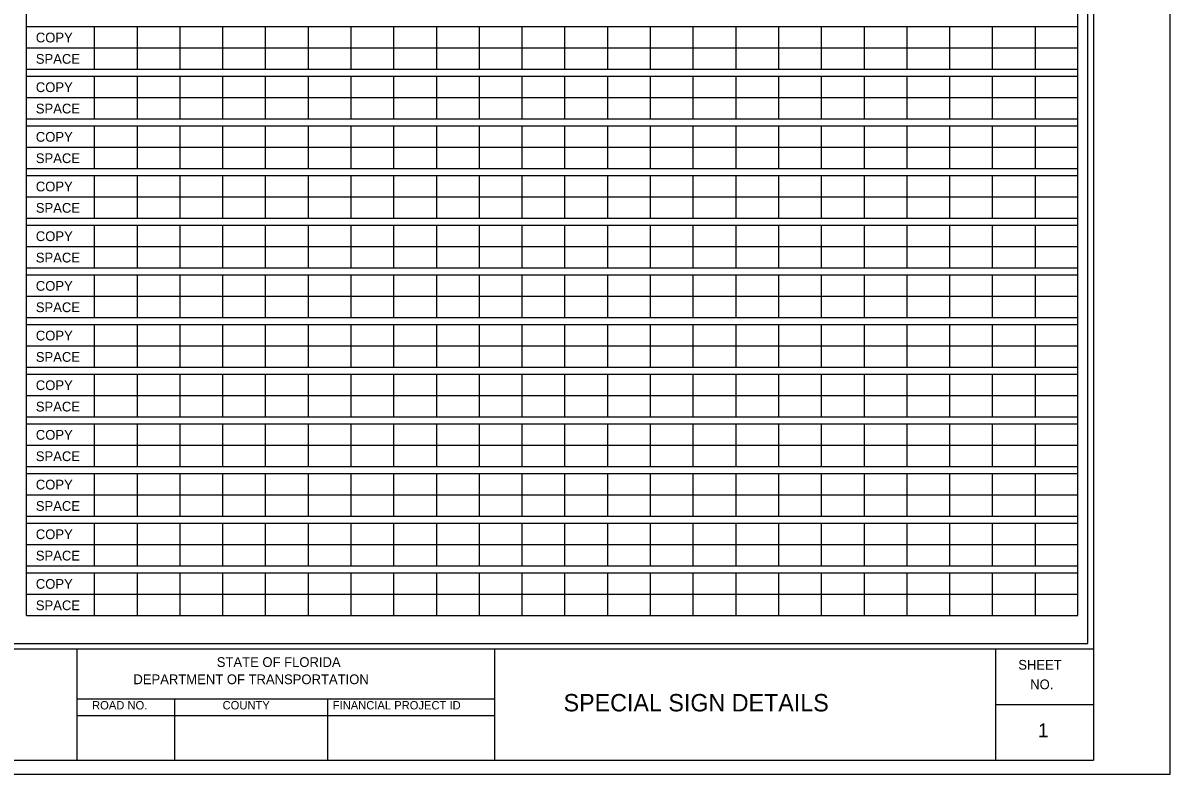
# Model space of a CAD drawing. Extents: x 17890484 to 17890754, y 17897495 to 17897992.
# Drawn here: x 17890564.9 to 17890645.6, y 17897495 to 17897547.8 of the extents above; entities that cross this region are included whole.
import ezdxf

# ---------------------------------------------------------------- set-up
doc = ezdxf.new("R2010")
doc.units = 0
for name, color, linetype in [('PlotBorder_dp', 7, 'Continuous'), ('SheetBorder_dp', 7, 'Continuous'), ('SheetLines_dp', 7, 'Continuous'), ('SheetLinesMisc1_dp', 7, 'Continuous'), ('SheetLinesMisc2_dp', 7, 'Continuous'), ('TextMinor', 7, 'Continuous'), ('TextMisc', 7, 'Continuous'), ('TextShtNo', 7, 'Continuous')]:
    doc.layers.add(name, color=color, linetype=linetype)

msp = doc.modelspace()

# ---------------------------------------------------------------- linework, layer by layer
at = {"layer": 'PlotBorder_dp'}
msp.add_lwpolyline([(17890483.9, 17897494.956), (17890645.649, 17897494.956), (17890645.649, 17897598.868), (17890483.9, 17897598.868)], close=True, dxfattribs=at)
at = {"layer": 'SheetBorder_dp'}
for p, q in [((17890640.258, 17897597.887), (17890640.258, 17897495.936)), ((17890489.292, 17897503.779), (17890640.258, 17897503.779)), ((17890489.292, 17897495.936), (17890640.258, 17897495.936))]:
    msp.add_line(p, q, dxfattribs=at)
at = {"layer": 'SheetLines_dp'}
for p, q in [((17890568.696, 17897503.779), (17890568.696, 17897495.936)), ((17890598.105, 17897495.936), (17890598.105, 17897503.779)), ((17890633.395, 17897495.936), (17890633.395, 17897503.779)), ((17890568.696, 17897500.25), (17890598.105, 17897500.25)), ((17890575.558, 17897500.25), (17890575.558, 17897495.936)), ((17890586.341, 17897500.25), (17890586.341, 17897495.936)), ((17890633.395, 17897499.858), (17890640.258, 17897499.858)), ((17890568.696, 17897499.073), (17890598.105, 17897499.073))]:
    msp.add_line(p, q, dxfattribs=at)
at = {"layer": 'SheetLinesMisc1_dp'}
for p, q in [((17890565.155, 17897547.581), (17890639.157, 17897547.581)), ((17890569.918, 17897547.581), (17890569.918, 17897544.575)), ((17890572.929, 17897547.581), (17890572.929, 17897544.575)), ((17890575.94, 17897547.581), (17890575.94, 17897544.575)), ((17890578.949, 17897547.581), (17890578.949, 17897544.575)), ((17890581.96, 17897547.581), (17890581.96, 17897544.575)), ((17890584.97, 17897547.581), (17890584.97, 17897544.575)), ((17890587.981, 17897547.581), (17890587.981, 17897544.575)), ((17890590.991, 17897547.581), (17890590.991, 17897544.575)), ((17890594.001, 17897547.581), (17890594.001, 17897544.575)), ((17890597.011, 17897547.581), (17890597.011, 17897544.575)), ((17890600.022, 17897547.581), (17890600.022, 17897544.575)), ((17890603.032, 17897547.581), (17890603.032, 17897544.575)), ((17890606.043, 17897547.581), (17890606.043, 17897544.575)), ((17890609.053, 17897547.581), (17890609.053, 17897544.575)), ((17890612.064, 17897547.581), (17890612.064, 17897544.575)), ((17890615.074, 17897547.581), (17890615.074, 17897544.575)), ((17890618.084, 17897547.581), (17890618.084, 17897544.575)), ((17890621.094, 17897547.581), (17890621.094, 17897544.575)), ((17890624.105, 17897547.581), (17890624.105, 17897544.575)), ((17890627.116, 17897547.581), (17890627.116, 17897544.575)), ((17890630.125, 17897547.581), (17890630.125, 17897544.575)), ((17890633.136, 17897547.581), (17890633.136, 17897544.575)), ((17890636.147, 17897547.581), (17890636.147, 17897544.575)), ((17890565.155, 17897546.078), (17890639.157, 17897546.078)), ((17890565.155, 17897544.575), (17890639.157, 17897544.575)), ((17890565.155, 17897544.084), (17890639.157, 17897544.084)), ((17890569.918, 17897544.084), (17890569.918, 17897541.078)), ((17890572.929, 17897544.084), (17890572.929, 17897541.078)), ((17890575.94, 17897544.084), (17890575.94, 17897541.078)), ((17890578.949, 17897544.084), (17890578.949, 17897541.078)), ((17890581.96, 17897544.084), (17890581.96, 17897541.078)), ((17890584.97, 17897544.084), (17890584.97, 17897541.078)), ((17890587.981, 17897544.084), (17890587.981, 17897541.078)), ((17890590.991, 17897544.084), (17890590.991, 17897541.078)), ((17890594.001, 17897544.084), (17890594.001, 17897541.078)), ((17890597.011, 17897544.084), (17890597.011, 17897541.078)), ((17890600.022, 17897544.084), (17890600.022, 17897541.078)), ((17890603.032, 17897544.084), (17890603.032, 17897541.078)), ((17890606.043, 17897544.084), (17890606.043, 17897541.078)), ((17890609.053, 17897544.084), (17890609.053, 17897541.078)), ((17890612.064, 17897544.084), (17890612.064, 17897541.078)), ((17890615.074, 17897544.084), (17890615.074, 17897541.078)), ((17890618.084, 17897544.084), (17890618.084, 17897541.078)), ((17890621.094, 17897544.084), (17890621.094, 17897541.078)), ((17890624.105, 17897544.084), (17890624.105, 17897541.078)), ((17890627.116, 17897544.084), (17890627.116, 17897541.078)), ((17890630.125, 17897544.084), (17890630.125, 17897541.078)), ((17890633.136, 17897544.084), (17890633.136, 17897541.078)), ((17890636.147, 17897544.084), (17890636.147, 17897541.078)), ((17890565.155, 17897542.581), (17890639.157, 17897542.581)), ((17890565.155, 17897541.078), (17890639.157, 17897541.078)), ((17890565.155, 17897540.588), (17890639.157, 17897540.588)), ((17890569.918, 17897540.588), (17890569.918, 17897537.582)), ((17890572.929, 17897540.588), (17890572.929, 17897537.582)), ((17890575.94, 17897540.588), (17890575.94, 17897537.582)), ((17890578.949, 17897540.588), (17890578.949, 17897537.582)), ((17890581.96, 17897540.588), (17890581.96, 17897537.582)), ((17890584.97, 17897540.588), (17890584.97, 17897537.582)), ((17890587.981, 17897540.588), (17890587.981, 17897537.582)), ((17890590.991, 17897540.588), (17890590.991, 17897537.582)), ((17890594.001, 17897540.588), (17890594.001, 17897537.582)), ((17890597.011, 17897540.588), (17890597.011, 17897537.582)), ((17890600.022, 17897540.588), (17890600.022, 17897537.582)), ((17890603.032, 17897540.588), (17890603.032, 17897537.582)), ((17890606.043, 17897540.588), (17890606.043, 17897537.582)), ((17890609.053, 17897540.588), (17890609.053, 17897537.582)), ((17890612.064, 17897540.588), (17890612.064, 17897537.582)), ((17890615.074, 17897540.588), (17890615.074, 17897537.582)), ((17890618.084, 17897540.588), (17890618.084, 17897537.582)), ((17890621.094, 17897540.588), (17890621.094, 17897537.582)), ((17890624.105, 17897540.588), (17890624.105, 17897537.582)), ((17890627.116, 17897540.588), (17890627.116, 17897537.582)), ((17890630.125, 17897540.588), (17890630.125, 17897537.582)), ((17890633.136, 17897540.588), (17890633.136, 17897537.582)), ((17890636.147, 17897540.588), (17890636.147, 17897537.582)), ((17890565.155, 17897539.085), (17890639.157, 17897539.085)), ((17890565.155, 17897537.582), (17890639.157, 17897537.582)), ((17890565.155, 17897537.091), (17890639.157, 17897537.091)), ((17890569.918, 17897537.091), (17890569.918, 17897534.085)), ((17890572.929, 17897537.091), (17890572.929, 17897534.085)), ((17890575.94, 17897537.091), (17890575.94, 17897534.085)), ((17890578.949, 17897537.091), (17890578.949, 17897534.085)), ((17890581.96, 17897537.091), (17890581.96, 17897534.085)), ((17890584.97, 17897537.091), (17890584.97, 17897534.085)), ((17890587.981, 17897537.091), (17890587.981, 17897534.085)), ((17890590.991, 17897537.091), (17890590.991, 17897534.085)), ((17890594.001, 17897537.091), (17890594.001, 17897534.085)), ((17890597.011, 17897537.091), (17890597.011, 17897534.085)), ((17890600.022, 17897537.091), (17890600.022, 17897534.085)), ((17890603.032, 17897537.091), (17890603.032, 17897534.085)), ((17890606.043, 17897537.091), (17890606.043, 17897534.085)), ((17890609.053, 17897537.091), (17890609.053, 17897534.085)), ((17890612.064, 17897537.091), (17890612.064, 17897534.085)), ((17890615.074, 17897537.091), (17890615.074, 17897534.085)), ((17890618.084, 17897537.091), (17890618.084, 17897534.085)), ((17890621.094, 17897537.091), (17890621.094, 17897534.085)), ((17890624.105, 17897537.091), (17890624.105, 17897534.085)), ((17890627.116, 17897537.091), (17890627.116, 17897534.085)), ((17890630.125, 17897537.091), (17890630.125, 17897534.085)), ((17890633.136, 17897537.091), (17890633.136, 17897534.085)), ((17890636.147, 17897537.091), (17890636.147, 17897534.085)), ((17890565.155, 17897535.588), (17890639.157, 17897535.589)), ((17890565.155, 17897534.085), (17890639.157, 17897534.085)), ((17890565.155, 17897533.595), (17890639.157, 17897533.595)), ((17890569.918, 17897533.595), (17890569.918, 17897530.589)), ((17890572.929, 17897533.595), (17890572.929, 17897530.589)), ((17890575.94, 17897533.595), (17890575.94, 17897530.589)), ((17890578.949, 17897533.595), (17890578.949, 17897530.589)), ((17890581.96, 17897533.595), (17890581.96, 17897530.589)), ((17890584.97, 17897533.595), (17890584.97, 17897530.589)), ((17890587.981, 17897533.595), (17890587.981, 17897530.589)), ((17890590.991, 17897533.595), (17890590.991, 17897530.589)), ((17890594.001, 17897533.595), (17890594.001, 17897530.589)), ((17890597.011, 17897533.595), (17890597.011, 17897530.589)), ((17890600.022, 17897533.595), (17890600.022, 17897530.589)), ((17890603.032, 17897533.595), (17890603.032, 17897530.589)), ((17890606.043, 17897533.595), (17890606.043, 17897530.589)), ((17890609.053, 17897533.595), (17890609.053, 17897530.589)), ((17890612.064, 17897533.595), (17890612.064, 17897530.589)), ((17890615.074, 17897533.595), (17890615.074, 17897530.589)), ((17890618.084, 17897533.595), (17890618.084, 17897530.589)), ((17890621.094, 17897533.595), (17890621.094, 17897530.589)), ((17890624.105, 17897533.595), (17890624.105, 17897530.589)), ((17890627.116, 17897533.595), (17890627.116, 17897530.589)), ((17890630.125, 17897533.595), (17890630.125, 17897530.589)), ((17890633.136, 17897533.595), (17890633.136, 17897530.589)), ((17890636.147, 17897533.595), (17890636.147, 17897530.589)), ((17890565.155, 17897532.092), (17890639.157, 17897532.092)), ((17890565.155, 17897530.589), (17890639.157, 17897530.589)), ((17890565.155, 17897530.099), (17890639.157, 17897530.099)), ((17890569.918, 17897530.099), (17890569.918, 17897527.092)), ((17890572.929, 17897530.099), (17890572.929, 17897527.092)), ((17890575.94, 17897530.099), (17890575.94, 17897527.092)), ((17890578.949, 17897530.099), (17890578.949, 17897527.092)), ((17890581.96, 17897530.099), (17890581.96, 17897527.092)), ((17890584.97, 17897530.099), (17890584.97, 17897527.092)), ((17890587.981, 17897530.099), (17890587.981, 17897527.092)), ((17890590.991, 17897530.099), (17890590.991, 17897527.092)), ((17890594.001, 17897530.099), (17890594.001, 17897527.092)), ((17890597.011, 17897530.099), (17890597.011, 17897527.092)), ((17890600.022, 17897530.099), (17890600.022, 17897527.092)), ((17890603.032, 17897530.099), (17890603.032, 17897527.092)), ((17890606.043, 17897530.099), (17890606.043, 17897527.092)), ((17890609.053, 17897530.099), (17890609.053, 17897527.092)), ((17890612.064, 17897530.099), (17890612.064, 17897527.092)), ((17890615.074, 17897530.099), (17890615.074, 17897527.092)), ((17890618.084, 17897530.099), (17890618.084, 17897527.092)), ((17890621.094, 17897530.099), (17890621.094, 17897527.092)), ((17890624.105, 17897530.099), (17890624.105, 17897527.092)), ((17890627.116, 17897530.099), (17890627.116, 17897527.092)), ((17890630.125, 17897530.099), (17890630.125, 17897527.092)), ((17890633.136, 17897530.099), (17890633.136, 17897527.092)), ((17890636.147, 17897530.099), (17890636.147, 17897527.092)), ((17890565.155, 17897528.595), (17890639.157, 17897528.595)), ((17890565.155, 17897527.092), (17890639.157, 17897527.092)), ((17890565.155, 17897526.602), (17890639.157, 17897526.602)), ((17890569.918, 17897526.602), (17890569.918, 17897523.595)), ((17890572.929, 17897526.602), (17890572.929, 17897523.595)), ((17890575.94, 17897526.602), (17890575.94, 17897523.595)), ((17890578.949, 17897526.602), (17890578.949, 17897523.595)), ((17890581.96, 17897526.602), (17890581.96, 17897523.595)), ((17890584.97, 17897526.602), (17890584.97, 17897523.595)), ((17890587.981, 17897526.602), (17890587.981, 17897523.595)), ((17890590.991, 17897526.602), (17890590.991, 17897523.595)), ((17890594.001, 17897526.602), (17890594.001, 17897523.595)), ((17890597.011, 17897526.602), (17890597.011, 17897523.595)), ((17890600.022, 17897526.602), (17890600.022, 17897523.595)), ((17890603.032, 17897526.602), (17890603.032, 17897523.595)), ((17890606.043, 17897526.602), (17890606.043, 17897523.595)), ((17890609.053, 17897526.602), (17890609.053, 17897523.595)), ((17890612.064, 17897526.602), (17890612.064, 17897523.595)), ((17890615.074, 17897526.602), (17890615.074, 17897523.595)), ((17890618.084, 17897526.602), (17890618.084, 17897523.595)), ((17890621.094, 17897526.602), (17890621.094, 17897523.595)), ((17890624.105, 17897526.602), (17890624.105, 17897523.595)), ((17890627.116, 17897526.602), (17890627.116, 17897523.595)), ((17890630.125, 17897526.602), (17890630.125, 17897523.595)), ((17890633.136, 17897526.602), (17890633.136, 17897523.595)), ((17890636.147, 17897526.602), (17890636.147, 17897523.595)), ((17890565.155, 17897525.099), (17890639.157, 17897525.099)), ((17890565.155, 17897523.595), (17890639.157, 17897523.595)), ((17890565.155, 17897523.105), (17890639.157, 17897523.105)), ((17890569.918, 17897523.105), (17890569.918, 17897520.099)), ((17890572.929, 17897523.105), (17890572.929, 17897520.099)), ((17890575.94, 17897523.105), (17890575.94, 17897520.099)), ((17890578.949, 17897523.105), (17890578.949, 17897520.099)), ((17890581.96, 17897523.105), (17890581.96, 17897520.099)), ((17890584.97, 17897523.105), (17890584.97, 17897520.099)), ((17890587.981, 17897523.105), (17890587.981, 17897520.099)), ((17890590.991, 17897523.105), (17890590.991, 17897520.099)), ((17890594.001, 17897523.105), (17890594.001, 17897520.099)), ((17890597.011, 17897523.105), (17890597.011, 17897520.099)), ((17890600.022, 17897523.105), (17890600.022, 17897520.099)), ((17890603.032, 17897523.105), (17890603.032, 17897520.099)), ((17890606.043, 17897523.105), (17890606.043, 17897520.099)), ((17890609.053, 17897523.105), (17890609.053, 17897520.099)), ((17890612.064, 17897523.105), (17890612.064, 17897520.099)), ((17890615.074, 17897523.105), (17890615.074, 17897520.099)), ((17890618.084, 17897523.105), (17890618.084, 17897520.099)), ((17890621.094, 17897523.105), (17890621.094, 17897520.099)), ((17890624.105, 17897523.105), (17890624.105, 17897520.099)), ((17890627.116, 17897523.105), (17890627.116, 17897520.099)), ((17890630.125, 17897523.105), (17890630.125, 17897520.099)), ((17890633.136, 17897523.105), (17890633.136, 17897520.099)), ((17890636.147, 17897523.105), (17890636.147, 17897520.099)), ((17890565.155, 17897521.602), (17890639.157, 17897521.602)), ((17890565.155, 17897520.099), (17890639.157, 17897520.099)), ((17890565.155, 17897519.609), (17890639.157, 17897519.609)), ((17890569.918, 17897519.609), (17890569.918, 17897516.603)), ((17890572.929, 17897519.609), (17890572.929, 17897516.603)), ((17890575.94, 17897519.609), (17890575.94, 17897516.603)), ((17890578.949, 17897519.609), (17890578.949, 17897516.603)), ((17890581.96, 17897519.609), (17890581.96, 17897516.603)), ((17890584.97, 17897519.609), (17890584.97, 17897516.603)), ((17890587.981, 17897519.609), (17890587.981, 17897516.603)), ((17890590.991, 17897519.609), (17890590.991, 17897516.603)), ((17890594.001, 17897519.609), (17890594.001, 17897516.603)), ((17890597.011, 17897519.609), (17890597.011, 17897516.603)), ((17890600.022, 17897519.609), (17890600.022, 17897516.603)), ((17890603.032, 17897519.609), (17890603.032, 17897516.603)), ((17890606.043, 17897519.609), (17890606.043, 17897516.603)), ((17890609.053, 17897519.609), (17890609.053, 17897516.603)), ((17890612.064, 17897519.609), (17890612.064, 17897516.603)), ((17890615.074, 17897519.609), (17890615.074, 17897516.603)), ((17890618.084, 17897519.609), (17890618.084, 17897516.603)), ((17890621.094, 17897519.609), (17890621.094, 17897516.603)), ((17890624.105, 17897519.609), (17890624.105, 17897516.603)), ((17890627.116, 17897519.609), (17890627.116, 17897516.603)), ((17890630.125, 17897519.609), (17890630.125, 17897516.603)), ((17890633.136, 17897519.609), (17890633.136, 17897516.603)), ((17890636.147, 17897519.609), (17890636.147, 17897516.603)), ((17890565.155, 17897518.105), (17890639.157, 17897518.106)), ((17890565.155, 17897516.603), (17890639.157, 17897516.603)), ((17890565.155, 17897516.112), (17890639.157, 17897516.112)), ((17890569.918, 17897516.112), (17890569.918, 17897513.106)), ((17890572.929, 17897516.112), (17890572.929, 17897513.106)), ((17890575.94, 17897516.112), (17890575.94, 17897513.106)), ((17890578.949, 17897516.112), (17890578.949, 17897513.106)), ((17890581.96, 17897516.112), (17890581.96, 17897513.106)), ((17890584.97, 17897516.112), (17890584.97, 17897513.106)), ((17890587.981, 17897516.112), (17890587.981, 17897513.106)), ((17890590.991, 17897516.112), (17890590.991, 17897513.106)), ((17890594.001, 17897516.112), (17890594.001, 17897513.106)), ((17890597.011, 17897516.112), (17890597.011, 17897513.106)), ((17890600.022, 17897516.112), (17890600.022, 17897513.106)), ((17890603.032, 17897516.112), (17890603.032, 17897513.106)), ((17890606.043, 17897516.112), (17890606.043, 17897513.106)), ((17890609.053, 17897516.112), (17890609.053, 17897513.106)), ((17890612.064, 17897516.112), (17890612.064, 17897513.106)), ((17890615.074, 17897516.112), (17890615.074, 17897513.106)), ((17890618.084, 17897516.112), (17890618.084, 17897513.106)), ((17890621.094, 17897516.112), (17890621.094, 17897513.106)), ((17890624.105, 17897516.112), (17890624.105, 17897513.106)), ((17890627.116, 17897516.112), (17890627.116, 17897513.106)), ((17890630.125, 17897516.112), (17890630.125, 17897513.106)), ((17890633.136, 17897516.112), (17890633.136, 17897513.106)), ((17890636.147, 17897516.112), (17890636.147, 17897513.106)), ((17890565.155, 17897514.609), (17890639.157, 17897514.609)), ((17890565.155, 17897513.106), (17890639.157, 17897513.106)), ((17890565.155, 17897512.616), (17890639.157, 17897512.616)), ((17890569.918, 17897512.616), (17890569.918, 17897509.609)), ((17890572.929, 17897512.616), (17890572.929, 17897509.609)), ((17890575.94, 17897512.616), (17890575.94, 17897509.609)), ((17890578.949, 17897512.616), (17890578.949, 17897509.609)), ((17890581.96, 17897512.616), (17890581.96, 17897509.609)), ((17890584.97, 17897512.616), (17890584.97, 17897509.609)), ((17890587.981, 17897512.616), (17890587.981, 17897509.609)), ((17890590.991, 17897512.616), (17890590.991, 17897509.609)), ((17890594.001, 17897512.616), (17890594.001, 17897509.609)), ((17890597.011, 17897512.616), (17890597.011, 17897509.609)), ((17890600.022, 17897512.616), (17890600.022, 17897509.609)), ((17890603.032, 17897512.616), (17890603.032, 17897509.609)), ((17890606.043, 17897512.616), (17890606.043, 17897509.609)), ((17890609.053, 17897512.616), (17890609.053, 17897509.609)), ((17890612.064, 17897512.616), (17890612.064, 17897509.609)), ((17890615.074, 17897512.616), (17890615.074, 17897509.609)), ((17890618.084, 17897512.616), (17890618.084, 17897509.609)), ((17890621.094, 17897512.616), (17890621.094, 17897509.609)), ((17890624.105, 17897512.616), (17890624.105, 17897509.609)), ((17890627.116, 17897512.616), (17890627.116, 17897509.609)), ((17890630.125, 17897512.616), (17890630.125, 17897509.609)), ((17890633.136, 17897512.616), (17890633.136, 17897509.609)), ((17890636.147, 17897512.616), (17890636.147, 17897509.609)), ((17890565.155, 17897511.112), (17890639.157, 17897511.112)), ((17890565.155, 17897509.609), (17890639.157, 17897509.609)), ((17890565.155, 17897509.119), (17890639.157, 17897509.119)), ((17890569.918, 17897509.119), (17890569.918, 17897506.112)), ((17890572.929, 17897509.119), (17890572.929, 17897506.112)), ((17890575.94, 17897509.119), (17890575.94, 17897506.112)), ((17890578.949, 17897509.119), (17890578.949, 17897506.112)), ((17890581.96, 17897509.119), (17890581.96, 17897506.112)), ((17890584.97, 17897509.119), (17890584.97, 17897506.112)), ((17890587.981, 17897509.119), (17890587.981, 17897506.112)), ((17890590.991, 17897509.119), (17890590.991, 17897506.112)), ((17890594.001, 17897509.119), (17890594.001, 17897506.112)), ((17890597.011, 17897509.119), (17890597.011, 17897506.112)), ((17890600.022, 17897509.119), (17890600.022, 17897506.112)), ((17890603.032, 17897509.119), (17890603.032, 17897506.112)), ((17890606.043, 17897509.119), (17890606.043, 17897506.112)), ((17890609.053, 17897509.119), (17890609.053, 17897506.112)), ((17890612.064, 17897509.119), (17890612.064, 17897506.112)), ((17890615.074, 17897509.119), (17890615.074, 17897506.112)), ((17890618.084, 17897509.119), (17890618.084, 17897506.112)), ((17890621.094, 17897509.119), (17890621.094, 17897506.112)), ((17890624.105, 17897509.119), (17890624.105, 17897506.112)), ((17890627.116, 17897509.119), (17890627.116, 17897506.112)), ((17890630.125, 17897509.119), (17890630.125, 17897506.112)), ((17890633.136, 17897509.119), (17890633.136, 17897506.112)), ((17890636.147, 17897509.119), (17890636.147, 17897506.112)), ((17890565.155, 17897507.615), (17890639.157, 17897507.615))]:
    msp.add_line(p, q, dxfattribs=at)
at = {"layer": 'SheetLinesMisc2_dp'}
for p, q in [((17890639.869, 17897504.15), (17890639.869, 17897597.807)), ((17890565.155, 17897506.112), (17890565.155, 17897572.057)), ((17890639.157, 17897506.112), (17890639.157, 17897572.057)), ((17890639.149, 17897525.518), (17890639.149, 17897525.552)), ((17890565.155, 17897506.112), (17890639.157, 17897506.112)), ((17890489.413, 17897504.15), (17890639.869, 17897504.15))]:
    msp.add_line(p, q, dxfattribs=at)

# ---------------------------------------------------------------- texts
at = {"layer": 'TextMinor'}
for s, p in [('COPY', (17890565.804, 17897546.457)), ('SPACE', (17890565.804, 17897544.954)), ('COPY', (17890565.804, 17897542.96)), ('SPACE', (17890565.804, 17897541.456)), ('COPY', (17890565.804, 17897539.464)), ('SPACE', (17890565.804, 17897537.961)), ('COPY', (17890565.804, 17897535.97)), ('SPACE', (17890565.804, 17897534.467)), ('COPY', (17890565.804, 17897532.471)), ('SPACE', (17890565.804, 17897530.967)), ('COPY', (17890565.804, 17897528.974)), ('SPACE', (17890565.804, 17897527.471)), ('COPY', (17890565.804, 17897525.477)), ('SPACE', (17890565.804, 17897523.973)), ('COPY', (17890565.804, 17897521.982)), ('SPACE', (17890565.804, 17897520.478)), ('COPY', (17890565.804, 17897518.488)), ('SPACE', (17890565.804, 17897516.984)), ('COPY', (17890565.804, 17897514.988)), ('SPACE', (17890565.804, 17897513.484)), ('COPY', (17890565.804, 17897511.492)), ('SPACE', (17890565.804, 17897509.988)), ('COPY', (17890565.804, 17897507.995)), ('SPACE', (17890565.804, 17897506.491))]:
    msp.add_text(s, height=0.6862, dxfattribs=at).set_placement(p)
at = {"layer": 'TextMisc'}
for s, height, p in [('STATE OF FLORIDA', 0.68621, (17890578.543, 17897502.495)), ('DEPARTMENT OF TRANSPORTATION', 0.68621, (17890572.674, 17897501.283)), ('SPECIAL SIGN DETAILS', 1.22537, (17890602.956, 17897499.365)), ('ROAD NO.', 0.5882, (17890569.764, 17897499.505)), ('COUNTY', 0.5882, (17890578.951, 17897499.505)), ('FINANCIAL PROJECT ID', 0.58818, (17890586.707, 17897499.505))]:
    msp.add_text(s, height=height, dxfattribs=at).set_placement(p)
for s, p in [('SHEET', (17890634.963, 17897502.303)), ('NO.', (17890635.803, 17897500.929))]:
    msp.add_text(s, height=0.6862, rotation=359.86066, dxfattribs=at).set_placement(p)
at = {"layer": 'TextShtNo'}
msp.add_text('1', height=0.98, dxfattribs=at).set_placement((17890636.358, 17897497.545))

doc.saveas('drawing.dxf')
